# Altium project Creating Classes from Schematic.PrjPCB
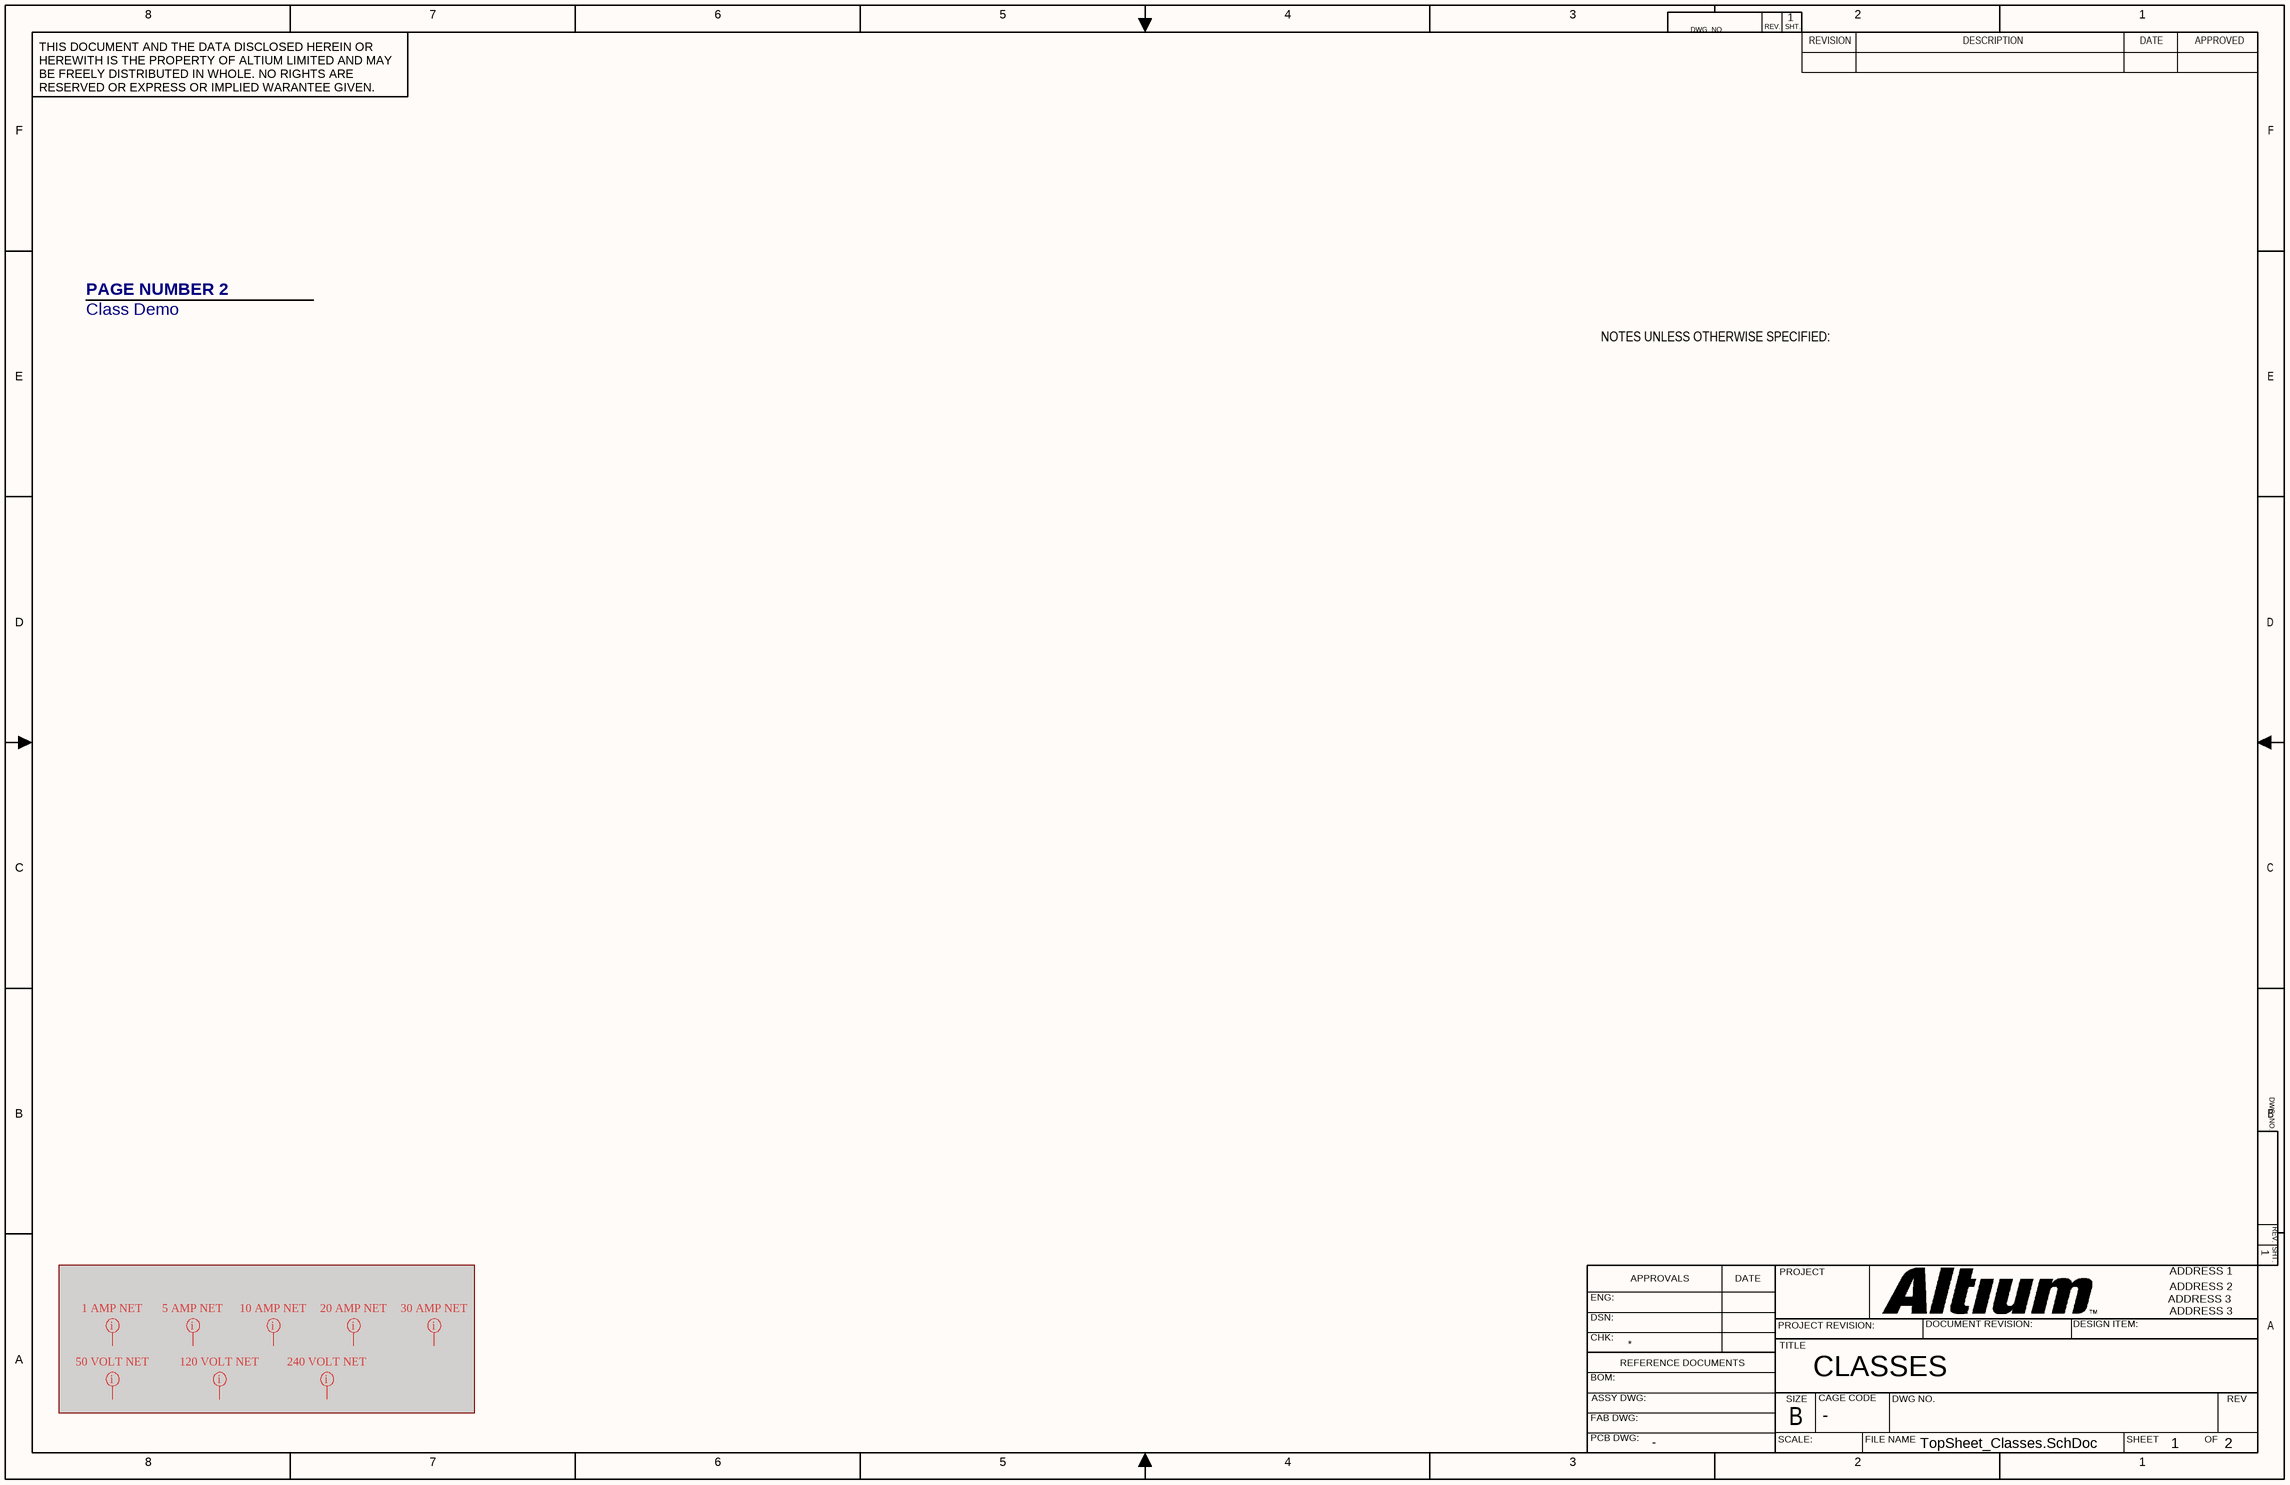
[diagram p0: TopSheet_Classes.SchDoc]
PCB_TITLE_1: Object Classes; PCB_SCALE: NONE; PCB_REV: -; PCB_PART_NUMBER: -; PCB_DWG_NO: -; PCB_ANG_TOL: +/-1/2; PCB_3_DEC_TOL: +/-.010; PCB_2_DEC_TOL: +/-.03; CONTRACT_NUMBER: -; CAGE_CODE: -
2 sheets, 12 parts. Net scope: global (net labels, ports and power ports of the same name join across sheets).
Board file: Classes.PcbDoc
Sheets:
  TopSheet_Classes.SchDoc
  Classes.SchDoc

## Sheet TopSheet_Classes.SchDoc: CLASSES
size 431 x 279 mm; Organization: ORGANIZATION; Address1: ADDRESS 1; Address2: ADDRESS 2; Address3: ADDRESS 3; Address4: ADDRESS 3; Revision: A; SheetNumber: 1; SheetTotal: 2

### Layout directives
net class AMP_1: (no net found under the mark)
net class AMP_10: (no net found under the mark)
net class AMP_20: (no net found under the mark)
net class AMP_30: (no net found under the mark)
net class VOLT_120: (no net found under the mark)
net class VOLT_240: (no net found under the mark)
net class VOLT_50: (no net found under the mark)
net class AMP_5: (no net found under the mark)

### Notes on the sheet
- PAGE NUMBER 2
- Class Demo
- NOTES UNLESS OTHERWISE SPECIFIED:

## Sheet Classes.SchDoc: CLASS DEMO
size 431 x 279 mm; Revision: A; SheetNumber: 2; SheetTotal: 2; Title2: FUSE BOARD; ENG_APP_DATE: --/--/--; DSN_APP_DATE: --/--/--; CHK_APP_DATE: --/--/--
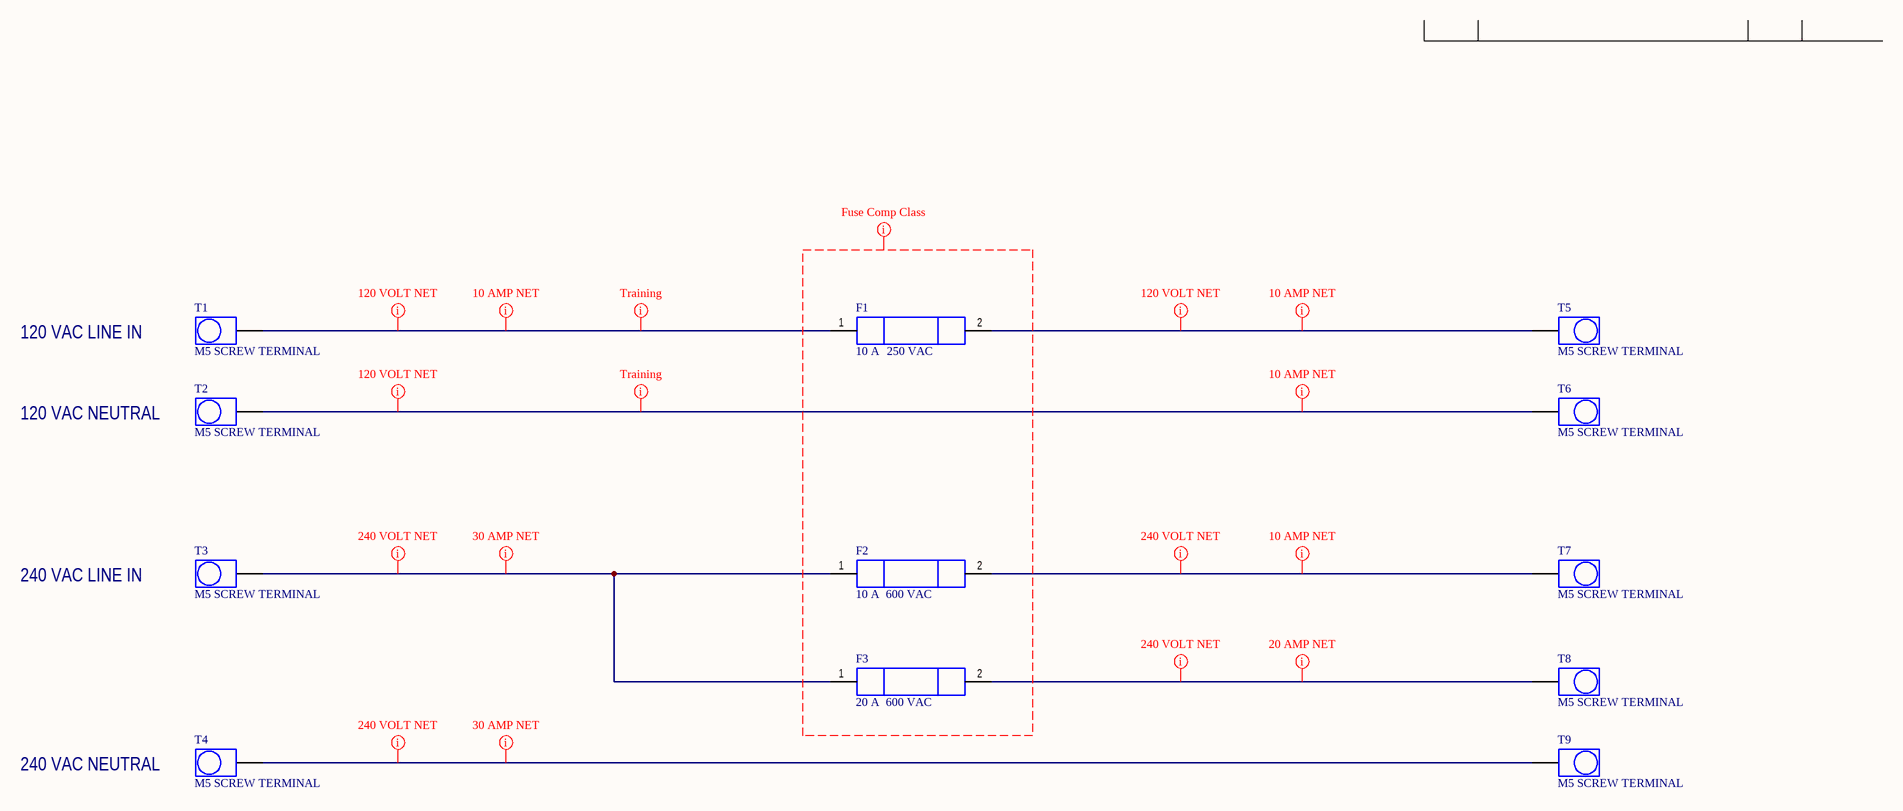
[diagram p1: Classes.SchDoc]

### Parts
F1  10 A  VOLTAGE_RATING: 250 VAC  [1/4 FUSE]
F2  10 A  VOLTAGE_RATING: 600 VAC  [13/32 FUSE]
F3  20 A  VOLTAGE_RATING: 600 VAC  [13/32 FUSE]
T1  M5 SCREW TERMINAL  [M5 TERMINAL]
T2  M5 SCREW TERMINAL  [M5 TERMINAL]
T3  M5 SCREW TERMINAL  [M5 TERMINAL]
T4  M5 SCREW TERMINAL  [M5 TERMINAL]
T5  M5 SCREW TERMINAL  [M5 TERMINAL]
T6  M5 SCREW TERMINAL  [M5 TERMINAL]
T7  M5 SCREW TERMINAL  [M5 TERMINAL]
T8  M5 SCREW TERMINAL  [M5 TERMINAL]
T9  M5 SCREW TERMINAL  [M5 TERMINAL]

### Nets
NetF1_1: F1.1 T1.1
NetF1_2: F1.2 T5.1
NetF2_1: F2.1 F3.1 T3.1
NetF2_2: F2.2 T7.1
NetF3_2: F3.2 T8.1
NetT2_1: T2.1 T6.1
NetT4_1: T4.1 T9.1

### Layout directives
net class VOLT_120: NetF1_1, NetF1_2, NetT2_1
net class VOLT_240: NetF2_1, NetF2_2, NetF3_2, NetT4_1
net class AMP_10: NetF1_1, NetF1_2, NetF2_2, NetT2_1
net class AMP_20: NetF3_2
net class AMP_30: NetF2_1, NetT4_1
net class TrainingClass: NetF1_1, NetT2_1
CompClassName: Fuse: (no net found under the mark)

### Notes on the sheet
- 120 VAC LINE IN
- 120 VAC NEUTRAL
- 240 VAC LINE IN
- 240 VAC NEUTRAL

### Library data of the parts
F1 = 10 AMP 250 VAC FUSE: MANUFACTURE: COOPER BUSSMAN; PART NUMBER: GBB-10-R
F2 = 10 AMP 600 VAC FUSE: MANUFACTURE: COOPER BUSSMAN; PART NUMBER: KTK-R-10
F3 = 20 AMP 600 VAC FUSE: MANUFACTURE: COOPER BUSSMAN; PART NUMBER: KTK-R-20
T1-T9 = TERMINAL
